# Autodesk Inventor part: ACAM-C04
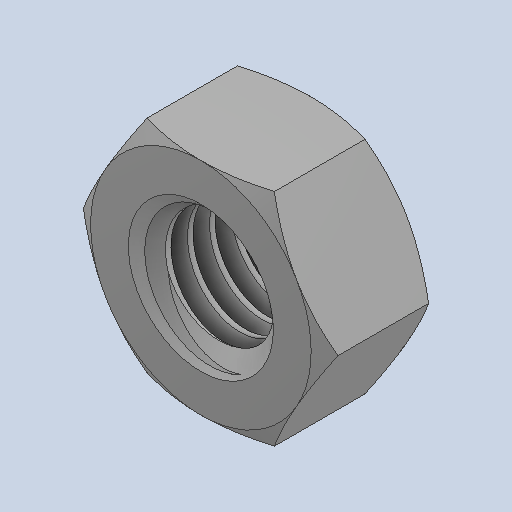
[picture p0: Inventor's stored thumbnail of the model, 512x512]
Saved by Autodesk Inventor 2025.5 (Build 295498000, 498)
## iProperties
Created: 2019-05
Part Number: ACAM-C04
Material: Genérico
Description: Tuerca hexagonal M5
Document SubType Name: Modeling
Designer: Luis M
Density: 1 g/cm^3
Appearance: Valor por defecto
Sending System: SolidWorks 2018
Preprocessor: SwSTEP 2.0
Material_BOM: Por especificar
Proceso_BOM: Comercial
Title: M5 Nut.STEP
Revision Number: HERHANGÝ
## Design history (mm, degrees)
feature "Kes-Süpür1"
node "Sólido1"
